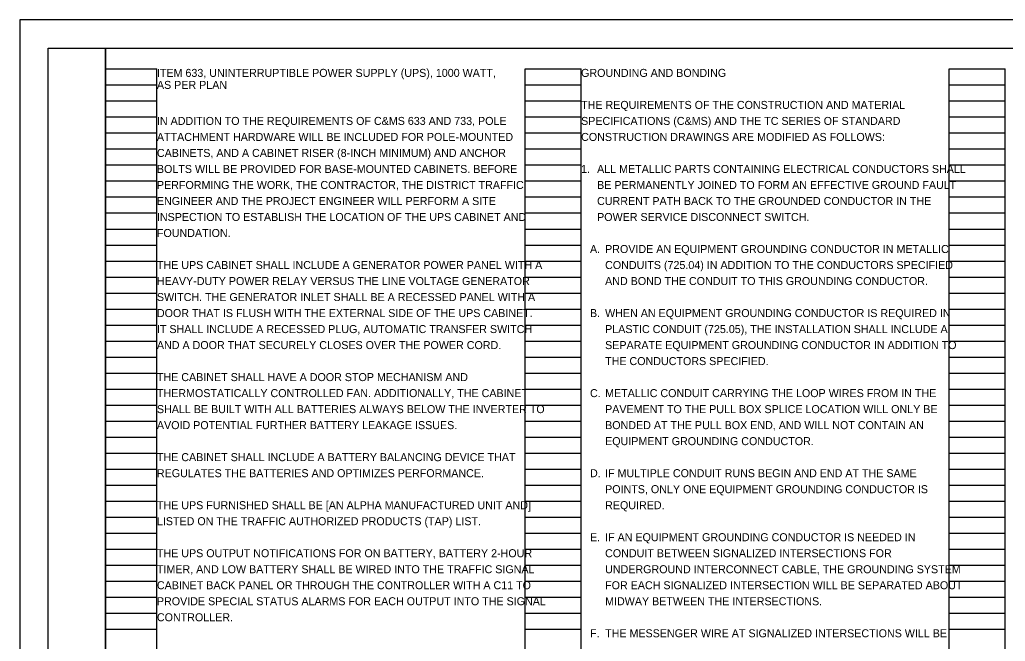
# Model space of a CAD drawing. Extents: x 0 to 34, y 0 to 22.
# Drawn here: x 0 to 17.24, y 11.13 to 22 of the extents above; entities that cross this region are included whole.
import ezdxf

# ---------------------------------------------------------------- set-up
doc = ezdxf.new("R2010")
doc.units = 0
for name, color, linetype in [('SH_Border', 7, 'Continuous'), ('SH_Cut_Line', 7, 'Continuous'), ('SH_Data', 7, 'Continuous'), ('SH_Text', 7, 'Continuous')]:
    doc.layers.add(name, color=color, linetype=linetype)

msp = doc.modelspace()

# ---------------------------------------------------------------- linework, layer by layer
at = {"layer": 'SH_Border'}
for points in [[(0.5, 21.5), (1.5, 21.5), (1.5, 0.5), (0.5, 0.5)], [(1.5, 21.5), (33.5, 21.5), (33.5, 0.5), (1.5, 0.5)]]:
    msp.add_lwpolyline(points, close=True, dxfattribs=at)
at = {"layer": 'SH_Cut_Line'}
msp.add_lwpolyline([(0, 0), (34, 0), (34, 22), (0, 22)], close=True, dxfattribs=at)
at = {"layer": 'SH_Data'}
for p, q in [((1.5, 0.98), (1.5, 21.14)), ((1.5, 21.14), (2.4, 21.14)), ((2.4, 0.98), (2.4, 21.14)), ((8.84, 0.98), (8.84, 21.14)), ((8.84, 21.14), (9.82, 21.14)), ((9.82, 0.98), (9.82, 21.14)), ((16.26, 0.98), (16.26, 21.14)), ((16.26, 21.14), (17.24, 21.14)), ((17.24, 0.98), (17.24, 21.14)), ((1.5, 20.86), (2.4, 20.86)), ((8.84, 20.86), (9.82, 20.86)), ((16.26, 20.86), (17.24, 20.86)), ((1.5, 20.58), (2.4, 20.58)), ((8.84, 20.58), (9.82, 20.58)), ((16.26, 20.58), (17.24, 20.58)), ((1.5, 20.3), (2.4, 20.3)), ((8.84, 20.3), (9.82, 20.3)), ((16.26, 20.3), (17.24, 20.3)), ((1.5, 20.02), (2.4, 20.02)), ((8.84, 20.02), (9.82, 20.02)), ((16.26, 20.02), (17.24, 20.02)), ((1.5, 19.74), (2.4, 19.74)), ((8.84, 19.74), (9.82, 19.74)), ((16.26, 19.74), (17.24, 19.74)), ((1.5, 19.46), (2.4, 19.46)), ((8.84, 19.46), (9.82, 19.46)), ((16.26, 19.46), (17.24, 19.46)), ((1.5, 19.18), (2.4, 19.18)), ((8.84, 19.18), (9.82, 19.18)), ((16.26, 19.18), (17.24, 19.18)), ((1.5, 18.9), (2.4, 18.9)), ((8.84, 18.9), (9.82, 18.9)), ((16.26, 18.9), (17.24, 18.9)), ((1.5, 18.62), (2.4, 18.62)), ((8.84, 18.62), (9.82, 18.62)), ((16.26, 18.62), (17.24, 18.62)), ((1.5, 18.34), (2.4, 18.34)), ((8.84, 18.34), (9.82, 18.34)), ((16.26, 18.34), (17.24, 18.34)), ((1.5, 18.06), (2.4, 18.06)), ((8.84, 18.06), (9.82, 18.06)), ((16.26, 18.06), (17.24, 18.06)), ((1.5, 17.78), (2.4, 17.78)), ((8.84, 17.78), (9.82, 17.78)), ((16.26, 17.78), (17.24, 17.78)), ((1.5, 17.5), (2.4, 17.5)), ((8.84, 17.5), (9.82, 17.5)), ((16.26, 17.5), (17.24, 17.5)), ((1.5, 17.22), (2.4, 17.22)), ((8.84, 17.22), (9.82, 17.22)), ((16.26, 17.22), (17.24, 17.22)), ((1.5, 16.94), (2.4, 16.94)), ((8.84, 16.94), (9.82, 16.94)), ((16.26, 16.94), (17.24, 16.94)), ((1.5, 16.66), (2.4, 16.66)), ((8.84, 16.66), (9.82, 16.66)), ((16.26, 16.66), (17.24, 16.66)), ((1.5, 16.38), (2.4, 16.38)), ((8.84, 16.38), (9.82, 16.38)), ((16.26, 16.38), (17.24, 16.38)), ((1.5, 16.1), (2.4, 16.1)), ((8.84, 16.1), (9.82, 16.1)), ((16.26, 16.1), (17.24, 16.1)), ((1.5, 15.82), (2.4, 15.82)), ((8.84, 15.82), (9.82, 15.82)), ((16.26, 15.82), (17.24, 15.82)), ((1.5, 15.54), (2.4, 15.54)), ((8.84, 15.54), (9.82, 15.54)), ((16.26, 15.54), (17.24, 15.54)), ((1.5, 15.26), (2.4, 15.26)), ((8.84, 15.26), (9.82, 15.26)), ((16.26, 15.26), (17.24, 15.26)), ((1.5, 14.98), (2.4, 14.98)), ((8.84, 14.98), (9.82, 14.98)), ((16.26, 14.98), (17.24, 14.98)), ((1.5, 14.7), (2.4, 14.7)), ((8.84, 14.7), (9.82, 14.7)), ((16.26, 14.7), (17.24, 14.7)), ((1.5, 14.42), (2.4, 14.42)), ((8.84, 14.42), (9.82, 14.42)), ((16.26, 14.42), (17.24, 14.42)), ((1.5, 14.14), (2.4, 14.14)), ((8.84, 14.14), (9.82, 14.14)), ((16.26, 14.14), (17.24, 14.14)), ((1.5, 13.86), (2.4, 13.86)), ((8.84, 13.86), (9.82, 13.86)), ((16.26, 13.86), (17.24, 13.86)), ((1.5, 13.58), (2.4, 13.58)), ((8.84, 13.58), (9.82, 13.58)), ((16.26, 13.58), (17.24, 13.58)), ((1.5, 13.3), (2.4, 13.3)), ((8.84, 13.3), (9.82, 13.3)), ((16.26, 13.3), (17.24, 13.3)), ((1.5, 13.02), (2.4, 13.02)), ((8.84, 13.02), (9.82, 13.02)), ((16.26, 13.02), (17.24, 13.02)), ((1.5, 12.74), (2.4, 12.74)), ((8.84, 12.74), (9.82, 12.74)), ((16.26, 12.74), (17.24, 12.74)), ((1.5, 12.46), (2.4, 12.46)), ((8.84, 12.46), (9.82, 12.46)), ((16.26, 12.46), (17.24, 12.46)), ((1.5, 12.18), (2.4, 12.18)), ((8.84, 12.18), (9.82, 12.18)), ((16.26, 12.18), (17.24, 12.18)), ((1.5, 11.9), (2.4, 11.9)), ((8.84, 11.9), (9.82, 11.9)), ((16.26, 11.9), (17.24, 11.9)), ((1.5, 11.62), (2.4, 11.62)), ((8.84, 11.62), (9.82, 11.62)), ((16.26, 11.62), (17.24, 11.62)), ((1.5, 11.34), (2.4, 11.34)), ((8.84, 11.34), (9.82, 11.34)), ((16.26, 11.34), (17.24, 11.34))]:
    msp.add_line(p, q, dxfattribs=at)

# ---------------------------------------------------------------- texts
at = {"layer": 'SH_Text'}
for s, p in [('ITEM 633, UNINTERRUPTIBLE POWER SUPPLY (UPS), 1000 WATT, ', (2.4, 21)), ('GROUNDING AND BONDING', (9.82, 21)), ('AS PER PLAN', (2.4, 20.79)), ('THE REQUIREMENTS OF THE CONSTRUCTION AND MATERIAL', (9.82, 20.44)), ('IN ADDITION TO THE REQUIREMENTS OF C&MS 633 AND 733, POLE ', (2.4, 20.16)), ('SPECIFICATIONS (C&MS) AND THE TC SERIES OF STANDARD ', (9.82, 20.16)), ('ATTACHMENT HARDWARE WILL BE INCLUDED FOR POLE-MOUNTED ', (2.4, 19.88)), ('CONSTRUCTION DRAWINGS ARE MODIFIED AS FOLLOWS:', (9.82, 19.88)), ('CABINETS, AND A CABINET RISER (8-INCH MINIMUM) AND ANCHOR ', (2.4, 19.6)), ('BOLTS WILL BE PROVIDED FOR BASE-MOUNTED CABINETS. BEFORE ', (2.4, 19.32)), ('1.  ', (9.82, 19.32)), ('ALL METALLIC PARTS CONTAINING ELECTRICAL CONDUCTORS SHALL ', (10.1, 19.32)), ('PERFORMING THE WORK, THE CONTRACTOR, THE DISTRICT TRAFFIC ', (2.4, 19.04)), ('BE PERMANENTLY JOINED TO FORM AN EFFECTIVE GROUND FAULT ', (10.1, 19.04)), ('ENGINEER AND THE PROJECT ENGINEER WILL PERFORM A SITE ', (2.4, 18.76)), ('CURRENT PATH BACK TO THE GROUNDED CONDUCTOR IN THE ', (10.1, 18.76)), ('INSPECTION TO ESTABLISH THE LOCATION OF THE UPS CABINET AND ', (2.4, 18.48)), ('POWER SERVICE DISCONNECT SWITCH.', (10.1, 18.48)), ('FOUNDATION.', (2.4, 18.2)), ('   A.', (9.82, 17.92)), ('PROVIDE AN EQUIPMENT GROUNDING CONDUCTOR IN METALLIC ', (10.24, 17.92)), ('THE UPS CABINET SHALL INCLUDE A GENERATOR POWER PANEL WITH A ', (2.4, 17.64)), ('CONDUITS (725.04) IN ADDITION TO THE CONDUCTORS SPECIFIED ', (10.24, 17.64)), ('HEAVY-DUTY POWER RELAY VERSUS THE LINE VOLTAGE GENERATOR ', (2.4, 17.36)), ('AND BOND THE CONDUIT TO THIS GROUNDING CONDUCTOR.', (10.24, 17.36)), ('SWITCH. THE GENERATOR INLET SHALL BE A RECESSED PANEL WITH A ', (2.4, 17.08)), ('DOOR THAT IS FLUSH WITH THE EXTERNAL SIDE OF THE UPS CABINET. ', (2.4, 16.8)), ('   B.', (9.82, 16.8)), ('WHEN AN EQUIPMENT GROUNDING CONDUCTOR IS REQUIRED IN ', (10.24, 16.8)), ('IT SHALL INCLUDE A RECESSED PLUG, AUTOMATIC TRANSFER SWITCH ', (2.4, 16.52)), ('PLASTIC CONDUIT (725.05), THE INSTALLATION SHALL INCLUDE A ', (10.24, 16.52)), ('AND A DOOR THAT SECURELY CLOSES OVER THE POWER CORD.', (2.4, 16.24)), ('SEPARATE EQUIPMENT GROUNDING CONDUCTOR IN ADDITION TO ', (10.24, 16.24)), ('THE CONDUCTORS SPECIFIED.', (10.24, 15.96)), ('THE CABINET SHALL HAVE A DOOR STOP MECHANISM AND ', (2.4, 15.68)), ('THERMOSTATICALLY CONTROLLED FAN. ADDITIONALLY, THE CABINET ', (2.4, 15.4)), ('   C.', (9.82, 15.4)), ('METALLIC CONDUIT CARRYING THE LOOP WIRES FROM IN THE ', (10.24, 15.4)), ('SHALL BE BUILT WITH ALL BATTERIES ALWAYS BELOW THE INVERTER TO ', (2.4, 15.12)), ('PAVEMENT TO THE PULL BOX SPLICE LOCATION WILL ONLY BE ', (10.24, 15.12)), ('AVOID POTENTIAL FURTHER BATTERY LEAKAGE ISSUES.', (2.4, 14.84)), ('BONDED AT THE PULL BOX END, AND WILL NOT CONTAIN AN ', (10.24, 14.84)), ('EQUIPMENT GROUNDING CONDUCTOR.', (10.24, 14.56)), ('THE CABINET SHALL INCLUDE A BATTERY BALANCING DEVICE THAT ', (2.4, 14.28)), ('REGULATES THE BATTERIES AND OPTIMIZES PERFORMANCE.', (2.4, 14)), ('   D.', (9.82, 14)), ('IF MULTIPLE CONDUIT RUNS BEGIN AND END AT THE SAME ', (10.24, 14)), ('POINTS, ONLY ONE EQUIPMENT GROUNDING CONDUCTOR IS ', (10.24, 13.72)), ('THE UPS FURNISHED SHALL BE [AN ALPHA MANUFACTURED UNIT AND] ', (2.4, 13.44)), ('REQUIRED.', (10.24, 13.44)), ('LISTED ON THE TRAFFIC AUTHORIZED PRODUCTS (TAP) LIST.', (2.4, 13.16)), ('   E.', (9.82, 12.88)), ('IF AN EQUIPMENT GROUNDING CONDUCTOR IS NEEDED IN ', (10.24, 12.88)), ('THE UPS OUTPUT NOTIFICATIONS FOR ON BATTERY, BATTERY 2-HOUR ', (2.4, 12.6)), ('CONDUIT BETWEEN SIGNALIZED INTERSECTIONS FOR ', (10.24, 12.6)), ('TIMER, AND LOW BATTERY SHALL BE WIRED INTO THE TRAFFIC SIGNAL ', (2.4, 12.32)), ('UNDERGROUND INTERCONNECT CABLE, THE GROUNDING SYSTEM ', (10.24, 12.32)), ('CABINET BACK PANEL OR THROUGH THE CONTROLLER WITH A C11 TO ', (2.4, 12.04)), ('FOR EACH SIGNALIZED INTERSECTION WILL BE SEPARATED ABOUT ', (10.24, 12.04)), ('PROVIDE SPECIAL STATUS ALARMS FOR EACH OUTPUT INTO THE SIGNAL ', (2.4, 11.76)), ('MIDWAY BETWEEN THE INTERSECTIONS.', (10.24, 11.76)), ('CONTROLLER.', (2.4, 11.48)), ('   F.', (9.82, 11.2)), ('THE MESSENGER WIRE AT SIGNALIZED INTERSECTIONS WILL BE ', (10.24, 11.2))]:
    msp.add_text(s, height=0.14, dxfattribs=at).set_placement(p)

doc.saveas('drawing.dxf')
